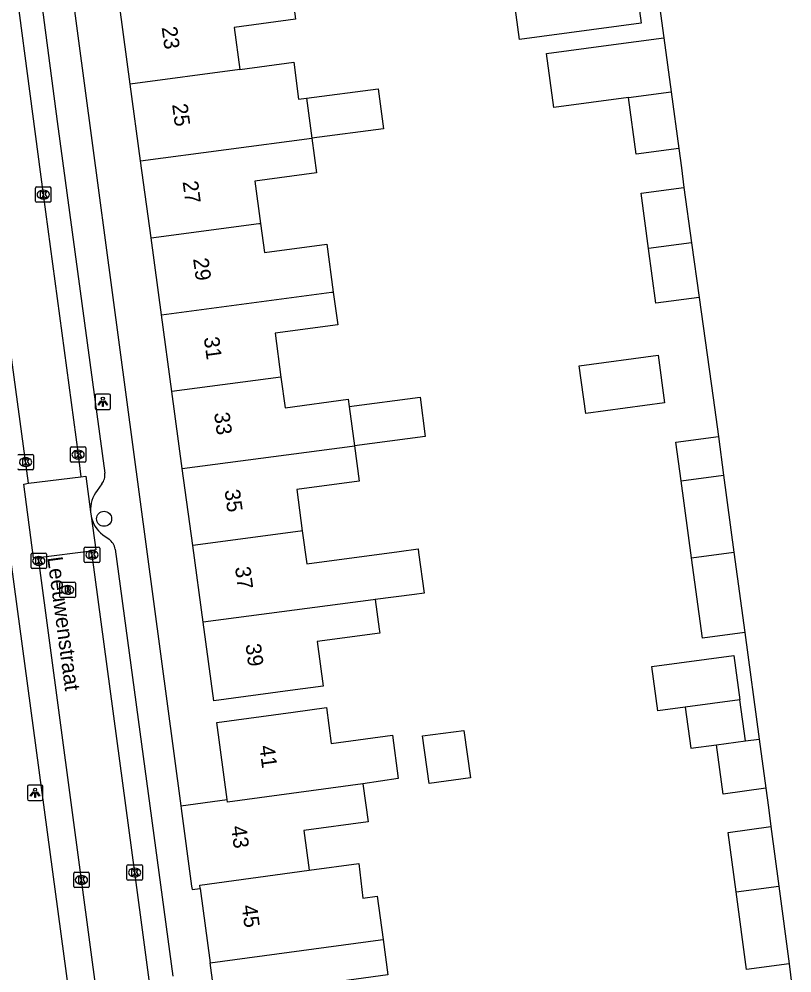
# Model space of a CAD drawing. Extents: x 163150 to 163546, y 380933 to 381635.
# Drawn here: x 163474.3 to 163524.5, y 381366 to 381427.9 of the extents above; entities that cross this region are included whole.
import ezdxf

# ---------------------------------------------------------------- set-up
doc = ezdxf.new("R2010")
doc.units = 0
for name, color, linetype in [('IMGEO_Boom', 7, 'Continuous'), ('IMGEO_Kolk', 7, 'Continuous'), ('IMGEO_Lichtpunt', 7, 'Continuous'), ('IMGEO_Openbare_ruimte_label', 7, 'Continuous'), ('IMGEO_Pand', 7, 'Continuous'), ('IMGEO_Pand_nummerreeks', 7, 'Continuous'), ('IMGEO_Rijbaan_lokaal_open', 7, 'Continuous'), ('IMGEO_Rioolput', 7, 'Continuous'), ('IMGEO_Voetpad_open', 7, 'Continuous')]:
    doc.layers.add(name, color=color, linetype=linetype)

msp = doc.modelspace()

# ---------------------------------------------------------------- linework, layer by layer
at = {"layer": 'IMGEO_Boom'}
msp.add_circle((163479.854, 381395.496), 0.489, dxfattribs=at)
at = {"layer": 'IMGEO_Kolk'}
for p, q in [((163475.408, 381416.117), (163475.408, 381416.969)), ((163475.483, 381417.043), (163476.335, 381417.043)), ((163476.409, 381416.969), (163476.409, 381416.117)), ((163475.919, 381416.263), (163475.894, 381416.263)), ((163475.896, 381416.823), (163475.921, 381416.823)), ((163476.335, 381416.043), (163475.483, 381416.043)), ((163477.742, 381400.167), (163478.594, 381400.167)), ((163474.337, 381399.678), (163475.189, 381399.678)), ((163475.263, 381399.604), (163475.263, 381398.752)), ((163477.667, 381399.241), (163477.667, 381400.093)), ((163478.155, 381399.947), (163478.18, 381399.947)), ((163478.668, 381400.093), (163478.668, 381399.241)), ((163474.75, 381399.458), (163474.775, 381399.458)), ((163478.594, 381399.167), (163477.742, 381399.167)), ((163478.178, 381399.387), (163478.153, 381399.387)), ((163475.189, 381398.678), (163474.337, 381398.678)), ((163474.773, 381398.898), (163474.748, 381398.898)), ((163478.569, 381392.732), (163478.569, 381393.584)), ((163478.644, 381393.658), (163479.496, 381393.658)), ((163479.057, 381393.438), (163479.082, 381393.438)), ((163479.57, 381393.584), (163479.57, 381392.732)), ((163475.113, 381392.339), (163475.113, 381393.191)), ((163475.188, 381393.265), (163476.04, 381393.265)), ((163475.601, 381393.045), (163475.626, 381393.045)), ((163476.114, 381393.191), (163476.114, 381392.339)), ((163479.08, 381392.878), (163479.055, 381392.878)), ((163476.04, 381392.265), (163475.188, 381392.265)), ((163475.624, 381392.485), (163475.599, 381392.485)), ((163479.496, 381392.658), (163478.644, 381392.658)), ((163481.339, 381372.106), (163481.339, 381372.958)), ((163481.414, 381373.032), (163482.266, 381373.032)), ((163482.34, 381372.958), (163482.34, 381372.106)), ((163477.885, 381371.623), (163477.885, 381372.475)), ((163477.96, 381372.549), (163478.812, 381372.549)), ((163478.373, 381372.329), (163478.398, 381372.329)), ((163478.886, 381372.475), (163478.886, 381371.623)), ((163481.827, 381372.812), (163481.852, 381372.812)), ((163478.396, 381371.769), (163478.371, 381371.769)), ((163482.266, 381372.032), (163481.414, 381372.032)), ((163481.85, 381372.252), (163481.825, 381372.252)), ((163478.812, 381371.549), (163477.96, 381371.549))]:
    msp.add_line(p, q, dxfattribs=at)
for points in [[(163475.408, 381416.117), (163475.408, 381416.969)], [(163475.483, 381417.043), (163476.335, 381417.043)], [(163476.409, 381416.969), (163476.409, 381416.117)], [(163475.729, 381416.743), (163475.852, 381416.743), (163475.852, 381416.592), (163475.982, 381416.743), (163476.146, 381416.743), (163476, 381416.592), (163476.153, 381416.343), (163476.001, 381416.343), (163475.916, 381416.507), (163475.852, 381416.44), (163475.852, 381416.343), (163475.729, 381416.343), (163475.729, 381416.743)], [(163476.335, 381416.043), (163475.483, 381416.043)], [(163477.742, 381400.167), (163478.594, 381400.167)], [(163474.337, 381399.678), (163475.189, 381399.678)], [(163475.263, 381399.604), (163475.263, 381398.752)], [(163477.667, 381399.241), (163477.667, 381400.093)], [(163477.988, 381399.867), (163478.111, 381399.867), (163478.111, 381399.716), (163478.241, 381399.867), (163478.405, 381399.867), (163478.259, 381399.716), (163478.412, 381399.467), (163478.26, 381399.467), (163478.175, 381399.631), (163478.111, 381399.564), (163478.111, 381399.467), (163477.988, 381399.467), (163477.988, 381399.867)], [(163478.668, 381400.093), (163478.668, 381399.241)], [(163474.583, 381399.378), (163474.706, 381399.378), (163474.706, 381399.227), (163474.836, 381399.378), (163475, 381399.378), (163474.854, 381399.227), (163475.007, 381398.978), (163474.855, 381398.978), (163474.77, 381399.142), (163474.706, 381399.075), (163474.706, 381398.978), (163474.583, 381398.978), (163474.583, 381399.378)], [(163478.594, 381399.167), (163477.742, 381399.167)], [(163475.189, 381398.678), (163474.337, 381398.678)], [(163478.569, 381392.732), (163478.569, 381393.584)], [(163478.644, 381393.658), (163479.496, 381393.658)], [(163478.89, 381393.358), (163479.013, 381393.358), (163479.013, 381393.207), (163479.143, 381393.358), (163479.307, 381393.358), (163479.161, 381393.207), (163479.314, 381392.958), (163479.162, 381392.958), (163479.077, 381393.122), (163479.013, 381393.055), (163479.013, 381392.958), (163478.89, 381392.958), (163478.89, 381393.358)], [(163479.57, 381393.584), (163479.57, 381392.732)], [(163475.113, 381392.339), (163475.113, 381393.191)], [(163475.188, 381393.265), (163476.04, 381393.265)], [(163475.434, 381392.965), (163475.557, 381392.965), (163475.557, 381392.814), (163475.687, 381392.965), (163475.851, 381392.965), (163475.705, 381392.814), (163475.858, 381392.565), (163475.706, 381392.565), (163475.621, 381392.729), (163475.557, 381392.662), (163475.557, 381392.565), (163475.434, 381392.565), (163475.434, 381392.965)], [(163476.114, 381393.191), (163476.114, 381392.339)], [(163476.04, 381392.265), (163475.188, 381392.265)], [(163479.496, 381392.658), (163478.644, 381392.658)], [(163481.339, 381372.106), (163481.339, 381372.958)], [(163481.414, 381373.032), (163482.266, 381373.032)], [(163482.34, 381372.958), (163482.34, 381372.106)], [(163477.885, 381371.623), (163477.885, 381372.475)], [(163477.96, 381372.549), (163478.812, 381372.549)], [(163478.886, 381372.475), (163478.886, 381371.623)], [(163481.66, 381372.732), (163481.783, 381372.732), (163481.783, 381372.581), (163481.913, 381372.732), (163482.077, 381372.732), (163481.931, 381372.581), (163482.084, 381372.332), (163481.932, 381372.332), (163481.847, 381372.496), (163481.783, 381372.429), (163481.783, 381372.332), (163481.66, 381372.332), (163481.66, 381372.732)], [(163478.206, 381372.249), (163478.329, 381372.249), (163478.329, 381372.098), (163478.459, 381372.249), (163478.623, 381372.249), (163478.477, 381372.098), (163478.63, 381371.849), (163478.478, 381371.849), (163478.393, 381372.013), (163478.329, 381371.946), (163478.329, 381371.849), (163478.206, 381371.849), (163478.206, 381372.249)], [(163482.266, 381372.032), (163481.414, 381372.032)], [(163478.812, 381371.549), (163477.96, 381371.549)]]:
    msp.add_lwpolyline(points, dxfattribs=at)
for centre, start, end in [((163475.485, 381416.967), 91.55205, 178.44795), ((163475.485, 381416.967), 91.55205, 178.44795), ((163476.333, 381416.967), 1.55205, 88.44795), ((163476.333, 381416.967), 1.55205, 88.44795), ((163475.485, 381416.119), 181.55205, 268.44795), ((163475.485, 381416.119), 181.55205, 268.44795), ((163476.333, 381416.119), 271.55205, 358.44795), ((163476.333, 381416.119), 271.55205, 358.44795), ((163477.744, 381400.091), 91.55205, 178.44795), ((163477.744, 381400.091), 91.55205, 178.44795), ((163478.592, 381400.091), 1.55205, 88.44795), ((163478.592, 381400.091), 1.55205, 88.44795), ((163474.339, 381399.602), 91.55205, 178.44795), ((163474.339, 381399.602), 91.55205, 178.44795), ((163475.187, 381399.602), 1.55205, 88.44795), ((163475.187, 381399.602), 1.55205, 88.44795), ((163477.744, 381399.243), 181.55205, 268.44795), ((163477.744, 381399.243), 181.55205, 268.44795), ((163478.592, 381399.243), 271.55205, 358.44795), ((163478.592, 381399.243), 271.55205, 358.44795), ((163474.339, 381398.754), 181.55205, 268.44795), ((163474.339, 381398.754), 181.55205, 268.44795), ((163475.187, 381398.754), 271.55205, 358.44795), ((163475.187, 381398.754), 271.55205, 358.44795), ((163478.646, 381393.582), 91.55205, 178.44795), ((163478.646, 381393.582), 91.55205, 178.44795), ((163479.494, 381393.582), 1.55205, 88.44795), ((163479.494, 381393.582), 1.55205, 88.44795), ((163475.19, 381393.189), 91.55205, 178.44795), ((163475.19, 381393.189), 91.55205, 178.44795), ((163476.038, 381393.189), 1.55205, 88.44795), ((163476.038, 381393.189), 1.55205, 88.44795), ((163478.646, 381392.734), 181.55205, 268.44795), ((163478.646, 381392.734), 181.55205, 268.44795), ((163479.494, 381392.734), 271.55205, 358.44795), ((163479.494, 381392.734), 271.55205, 358.44795), ((163475.19, 381392.341), 181.55205, 268.44795), ((163475.19, 381392.341), 181.55205, 268.44795), ((163476.038, 381392.341), 271.55205, 358.44795), ((163476.038, 381392.341), 271.55205, 358.44795), ((163481.416, 381372.956), 91.55205, 178.44795), ((163481.416, 381372.956), 91.55205, 178.44795), ((163482.264, 381372.956), 1.55205, 88.44795), ((163482.264, 381372.956), 1.55205, 88.44795), ((163477.962, 381372.473), 91.55205, 178.44795), ((163477.962, 381372.473), 91.55205, 178.44795), ((163478.81, 381372.473), 1.55205, 88.44795), ((163478.81, 381372.473), 1.55205, 88.44795), ((163481.416, 381372.108), 181.55205, 268.44795), ((163481.416, 381372.108), 181.55205, 268.44795), ((163482.264, 381372.108), 271.55205, 358.44795), ((163482.264, 381372.108), 271.55205, 358.44795), ((163477.962, 381371.625), 181.55205, 268.44795), ((163477.962, 381371.625), 181.55205, 268.44795), ((163478.81, 381371.625), 271.55205, 358.44795), ((163478.81, 381371.625), 271.55205, 358.44795)]:
    msp.add_arc(centre, 0.0765, start, end, dxfattribs=at)
for centre, major_axis, ratio, start_param, end_param in [((163475.895, 381416.543), (-0.387, 0.002), 0.722429, 4.712389, 7.853982), ((163475.92, 381416.543), (-0.39, 0.002), 0.717154, 1.570796, 4.712389), ((163478.154, 381399.667), (-0.387, 0.002), 0.722429, 4.712389, 7.853982), ((163478.179, 381399.667), (-0.39, 0.002), 0.717154, 1.570796, 4.712389), ((163474.749, 381399.178), (-0.387, 0.002), 0.722429, 4.712389, 7.853982), ((163474.774, 381399.178), (-0.39, 0.002), 0.717154, 1.570796, 4.712389), ((163479.056, 381393.158), (-0.387, 0.002), 0.722429, 4.712389, 7.853982), ((163479.081, 381393.158), (-0.39, 0.002), 0.717154, 1.570796, 4.712389), ((163475.6, 381392.765), (-0.387, 0.002), 0.722429, 4.712389, 7.853982), ((163475.625, 381392.765), (-0.39, 0.002), 0.717154, 1.570796, 4.712389), ((163478.372, 381372.049), (-0.387, 0.002), 0.722429, 4.712389, 7.853982), ((163478.397, 381372.049), (-0.39, 0.002), 0.717154, 1.570796, 4.712389), ((163481.826, 381372.532), (-0.387, 0.002), 0.722429, 4.712389, 7.853982), ((163481.851, 381372.532), (-0.39, 0.002), 0.717154, 1.570796, 4.712389)]:
    msp.add_ellipse(centre, major_axis=major_axis, ratio=ratio, start_param=start_param, end_param=end_param, dxfattribs=at)
at = {"layer": 'IMGEO_Lichtpunt'}
for p, q in [((163479.275, 381403.5), (163479.275, 381402.693)), ((163479.275, 381403.5), (163479.275, 381402.693)), ((163480.177, 381403.595), (163479.369, 381403.595)), ((163480.177, 381403.595), (163479.369, 381403.595)), ((163480.271, 381402.693), (163480.271, 381403.5)), ((163480.271, 381402.693), (163480.271, 381403.5)), ((163479.369, 381402.599), (163480.177, 381402.599)), ((163479.369, 381402.599), (163480.177, 381402.599)), ((163474.879, 381378.112), (163474.879, 381377.305)), ((163474.879, 381378.112), (163474.879, 381377.305)), ((163475.781, 381378.207), (163474.973, 381378.207)), ((163475.781, 381378.207), (163474.973, 381378.207)), ((163475.875, 381377.305), (163475.875, 381378.112)), ((163475.875, 381377.305), (163475.875, 381378.112)), ((163474.973, 381377.211), (163475.781, 381377.211)), ((163474.973, 381377.211), (163475.781, 381377.211))]:
    msp.add_line(p, q, dxfattribs=at)
for points in [[(163479.649, 381403.164), (163479.688, 381403.136), (163479.5, 381402.874), (163479.462, 381402.901), (163479.649, 381403.164)], [(163479.751, 381403.116), (163479.798, 381403.116), (163479.798, 381402.794), (163479.751, 381402.794), (163479.751, 381403.116)], [(163479.861, 381403.136), (163479.899, 381403.163), (163480.086, 381402.901), (163480.047, 381402.873), (163479.861, 381403.136)], [(163475.253, 381377.776), (163475.292, 381377.748), (163475.104, 381377.486), (163475.066, 381377.513), (163475.253, 381377.776)], [(163475.355, 381377.728), (163475.402, 381377.728), (163475.402, 381377.406), (163475.355, 381377.406), (163475.355, 381377.728)], [(163475.465, 381377.748), (163475.503, 381377.775), (163475.69, 381377.513), (163475.651, 381377.485), (163475.465, 381377.748)]]:
    msp.add_lwpolyline(points, dxfattribs=at)
for centre in [(163479.774, 381403.298), (163475.378, 381377.91)]:
    msp.add_circle(centre, 0.0994, dxfattribs=at)
for centre, start, end in [((163479.369, 381403.5), 90, 180), ((163479.369, 381403.5), 90, 180), ((163480.177, 381403.5), 0, 90), ((163480.177, 381403.5), 0, 90), ((163479.369, 381402.693), 180, 270), ((163479.369, 381402.693), 180, 270), ((163480.177, 381402.693), 270, 0), ((163480.177, 381402.693), 270, 360), ((163474.973, 381378.112), 90, 180), ((163474.973, 381378.112), 90, 180), ((163475.781, 381378.112), 0, 90), ((163475.781, 381378.112), 0, 90), ((163474.973, 381377.305), 180, 270), ((163474.973, 381377.305), 180, 270), ((163475.781, 381377.305), 270, 0), ((163475.781, 381377.305), 270, 360)]:
    msp.add_arc(centre, 0.0946, start, end, dxfattribs=at)
at = {"layer": 'IMGEO_Pand'}
for points in [[(163506.833, 381426.603), (163506.355, 381430.159), (163514.248, 381431.22), (163514.726, 381427.665), (163506.833, 381426.603)], [(163491.974, 381430.18), (163492.276, 381427.934), (163488.3, 381427.4), (163488.668, 381424.662)], [(163481.545, 381423.722), (163480.867, 381428.714)], [(163513.895, 381422.846), (163509.052, 381422.198), (163508.58, 381425.707), (163512.591, 381426.247), (163516.19, 381426.731)], [(163516.19, 381426.731), (163516.67, 381423.217)], [(163488.668, 381424.662), (163492.165, 381425.131), (163492.482, 381422.733), (163492.992, 381422.801)], [(163488.668, 381424.662), (163481.545, 381423.722)], [(163482.223, 381418.73), (163481.545, 381423.722)], [(163492.992, 381422.801), (163497.657, 381423.416), (163498.001, 381420.813), (163493.341, 381420.198)], [(163513.895, 381422.846), (163516.67, 381423.217)], [(163516.67, 381423.217), (163517.164, 381419.527)], [(163492.992, 381422.801), (163493.341, 381420.198)], [(163517.164, 381419.527), (163514.388, 381419.161), (163513.895, 381422.846)], [(163482.223, 381418.73), (163493.341, 381420.198)], [(163493.341, 381420.198), (163493.642, 381417.959), (163489.65, 381417.423), (163490.019, 381414.678)], [(163482.902, 381413.738), (163482.223, 381418.73)], [(163515.206, 381413.044), (163514.724, 381416.647), (163517.5, 381417.013)], [(163517.5, 381417.013), (163517.982, 381413.416)], [(163482.902, 381413.738), (163489.893, 381414.661), (163490.019, 381414.678)], [(163490.019, 381414.678), (163490.274, 381412.777), (163494.319, 381413.32), (163494.736, 381410.219)], [(163483.579, 381408.747), (163482.902, 381413.738)], [(163517.982, 381413.416), (163515.206, 381413.044)], [(163517.982, 381413.416), (163518.483, 381409.86)], [(163518.483, 381409.86), (163515.682, 381409.485), (163515.206, 381413.044)], [(163483.579, 381408.747), (163494.619, 381410.204), (163494.736, 381410.219)], [(163494.736, 381410.219), (163495.021, 381408.095), (163490.955, 381407.549), (163491.339, 381404.69)], [(163484.258, 381403.755), (163483.579, 381408.747)], [(163510.705, 381405.428), (163515.819, 381406.117), (163516.237, 381403.016), (163511.122, 381402.327), (163510.705, 381405.428)], [(163491.339, 381404.69), (163484.258, 381403.755)], [(163491.339, 381404.69), (163491.605, 381402.71), (163495.699, 381403.26), (163495.761, 381402.794)], [(163484.935, 381398.764), (163484.258, 381403.755)], [(163495.761, 381402.794), (163500.373, 381403.403), (163500.71, 381400.847), (163496.104, 381400.239)], [(163495.761, 381402.794), (163496.104, 381400.239)], [(163517.321, 381397.955), (163516.983, 381400.466), (163519.738, 381400.837)], [(163519.738, 381400.837), (163520.077, 381398.319)], [(163484.935, 381398.764), (163495.97, 381400.221), (163496.104, 381400.239)], [(163496.104, 381400.239), (163496.414, 381397.933), (163492.36, 381397.389), (163492.72, 381394.71)], [(163485.614, 381393.772), (163484.935, 381398.764)], [(163517.321, 381397.955), (163520.077, 381398.319)], [(163520.077, 381398.319), (163520.748, 381393.329)], [(163517.992, 381392.965), (163517.321, 381397.955)], [(163492.72, 381394.71), (163492.602, 381394.694), (163485.614, 381393.772)], [(163492.72, 381394.71), (163493.007, 381392.571), (163499.015, 381393.378), (163500.244, 381393.543), (163500.275, 381393.303), (163500.627, 381390.674), (163500, 381390.591), (163497.459, 381390.255)], [(163486.291, 381388.781), (163485.614, 381393.772)], [(163517.992, 381392.965), (163520.748, 381393.329)], [(163521.449, 381388.117), (163518.694, 381387.746), (163517.992, 381392.965)], [(163520.748, 381393.329), (163521.449, 381388.117)], [(163497.459, 381390.255), (163497.718, 381388.322), (163497.752, 381388.068), (163493.695, 381387.523), (163494.084, 381384.631), (163491.941, 381384.341), (163486.986, 381383.668), (163486.291, 381388.781)], [(163497.459, 381390.255), (163497.322, 381390.237), (163486.291, 381388.781)], [(163517.586, 381383.268), (163515.807, 381383.029), (163515.421, 381385.905), (163520.743, 381386.62), (163521.129, 381383.744)], [(163521.129, 381383.744), (163517.586, 381383.268)], [(163521.488, 381381.076), (163521.129, 381383.744)], [(163487.847, 381377.266), (163487.174, 381382.276), (163492.13, 381382.945), (163494.29, 381383.237), (163494.603, 381380.905), (163498.578, 381381.439), (163498.956, 381378.626), (163496.657, 381378.292)], [(163517.586, 381383.268), (163517.945, 381380.599), (163519.608, 381380.823)], [(163503.217, 381381.762), (163503.639, 381378.681), (163500.958, 381378.314), (163500.536, 381381.395), (163503.217, 381381.762)], [(163519.608, 381380.823), (163521.488, 381381.076)], [(163521.488, 381381.076), (163522.383, 381381.196)], [(163522.383, 381381.196), (163522.812, 381378)], [(163522.812, 381378), (163520.037, 381377.626), (163519.608, 381380.823)], [(163496.657, 381378.292), (163487.869, 381377.103), (163487.847, 381377.266)], [(163496.657, 381378.292), (163496.989, 381375.825), (163492.827, 381375.266), (163493.175, 381372.676)], [(163484.837, 381376.861), (163487.847, 381377.266)], [(163484.837, 381376.861), (163484.859, 381376.696), (163485.538, 381371.644), (163485.566, 381371.433), (163486.09, 381371.504)], [(163520.891, 381371.273), (163520.371, 381375.139), (163523.145, 381375.513)], [(163523.145, 381375.513), (163523.654, 381371.653)], [(163493.175, 381372.676), (163496.399, 381373.112), (163496.661, 381370.866), (163497.59, 381370.991), (163497.967, 381368.18)], [(163486.09, 381371.504), (163486.062, 381371.715), (163493.175, 381372.676)], [(163486.09, 381371.504), (163486.74, 381366.662)], [(163520.891, 381371.273), (163523.654, 381371.653)], [(163524.321, 381366.6), (163521.57, 381366.228), (163520.891, 381371.273)], [(163523.654, 381371.653), (163524.321, 381366.6)], [(163486.74, 381366.662), (163497.804, 381368.158), (163497.967, 381368.18)], [(163497.967, 381368.18), (163498.276, 381365.88), (163494.156, 381365.327), (163494.527, 381362.57)], [(163487.388, 381361.841), (163486.74, 381366.662)]]:
    msp.add_lwpolyline(points, dxfattribs=at)
at = {"layer": 'IMGEO_Rijbaan_lokaal_open'}
for points in [[(163470.778, 381454.762), (163470.878, 381454.101), (163473.318, 381436.048), (163475.908, 381416.544), (163478.167, 381399.667), (163478.336, 381398.227)], [(163474.95, 381397.812), (163472.424, 381416.369), (163471.932, 381420.183), (163469.84, 381435.559), (163467.375, 381453.632), (163467.333, 381454.278)], [(163513.109, 381449.351), (163513.265, 381448.139), (163516.19, 381426.731)], [(163517.164, 381419.527), (163517.33, 381418.283), (163517.5, 381417.013)], [(163518.483, 381409.86), (163519.399, 381403.356), (163519.738, 381400.837)], [(163475.57, 381392.982), (163475.27, 381392.965), (163474.636, 381397.753), (163474.95, 381397.812)], [(163474.95, 381397.812), (163478.336, 381398.227)], [(163478.336, 381398.227), (163478.665, 381398.259), (163478.975, 381395.958)], [(163478.975, 381395.958), (163479.015, 381395.662)], [(163479.015, 381395.662), (163479.31, 381393.474), (163479.013, 381393.424)], [(163475.57, 381392.982), (163479.013, 381393.424)], [(163479.013, 381393.424), (163479.069, 381393.155), (163481.839, 381372.532), (163484.475, 381352.776), (163487.265, 381332.107), (163487.676, 381329.103)], [(163484.25, 381328.608), (163483.846, 381331.616), (163481.014, 381352.472), (163478.387, 381372.049), (163475.613, 381392.784), (163475.57, 381392.982)], [(163521.449, 381388.117), (163522.383, 381381.196)], [(163522.812, 381378), (163522.981, 381376.759), (163523.145, 381375.513)], [(163524.321, 381366.6), (163524.509, 381365.17)]]:
    msp.add_lwpolyline(points, dxfattribs=at)
at = {"layer": 'IMGEO_Rioolput'}
for p, q in [((163476.992, 381390.457), (163476.992, 381391.309)), ((163477.067, 381391.383), (163477.919, 381391.383)), ((163477.48, 381391.163), (163477.505, 381391.163)), ((163477.993, 381391.309), (163477.993, 381390.457)), ((163477.919, 381390.383), (163477.067, 381390.383)), ((163477.503, 381390.603), (163477.478, 381390.603))]:
    msp.add_line(p, q, dxfattribs=at)
for points in [[(163476.992, 381390.457), (163476.992, 381391.309)], [(163477.067, 381391.383), (163477.919, 381391.383)], [(163477.581, 381391.081), (163477.329, 381391.083), (163477.329, 381390.683)], [(163477.507, 381391.002), (163477.453, 381391.002), (163477.453, 381390.921)], [(163477.453, 381390.921), (163477.505, 381390.921)], [(163477.993, 381391.309), (163477.993, 381390.457)], [(163477.919, 381390.383), (163477.067, 381390.383)], [(163477.329, 381390.683), (163477.453, 381390.683), (163477.453, 381390.845), (163477.464, 381390.845)], [(163477.511, 381390.816), (163477.582, 381390.683), (163477.722, 381390.683), (163477.657, 381390.809)]]:
    msp.add_lwpolyline(points, dxfattribs=at)
for centre, radius, start, end in [((163477.069, 381391.307), 0.0765, 91.55205, 178.44795), ((163477.069, 381391.307), 0.0765, 91.55205, 178.44795), ((163477.489, 381391.11), 0.19, 274.7715, 282.96867), ((163477.513, 381390.906), 0.0964, 77.00612, 93.18647), ((163477.527, 381390.963), 0.0378, 276.66336, 79.67722), ((163477.58, 381390.971), 0.109, 350.36119, 89.41601), ((163477.578, 381390.971), 0.112, 277.58423, 350.98172), ((163477.562, 381390.756), 0.108, 29.51342, 73.79051), ((163477.917, 381391.307), 0.0765, 1.55205, 88.44795), ((163477.917, 381391.307), 0.0765, 1.55205, 88.44795), ((163477.069, 381390.459), 0.0765, 181.55205, 268.44795), ((163477.069, 381390.459), 0.0765, 181.55205, 268.44795), ((163477.463, 381390.792), 0.0533, 26.02933, 88.69889), ((163477.917, 381390.459), 0.0765, 271.55205, 358.44795), ((163477.917, 381390.459), 0.0765, 271.55205, 358.44795)]:
    msp.add_arc(centre, radius, start, end, dxfattribs=at)
for centre, major_axis, ratio, start_param, end_param in [((163477.479, 381390.883), (-0.387, 0.002), 0.722429, 4.712389, 7.853982), ((163477.504, 381390.883), (-0.39, 0.002), 0.717154, 1.570796, 4.712389)]:
    msp.add_ellipse(centre, major_axis=major_axis, ratio=ratio, start_param=start_param, end_param=end_param, dxfattribs=at)
at = {"layer": 'IMGEO_Voetpad_open'}
for points in [[(163474.607, 381453.41), (163484.837, 381376.861)], [(163475.395, 381432.031), (163476.816, 381421.298), (163479.901, 381398.456)], [(163480.813, 381340.703), (163470.252, 381419.099)], [(163479.702, 381397.757), (163479.399, 381397.332)], [(163479.767, 381394.465), (163480.177, 381394.171)], [(163480.585, 381393.522), (163484.323, 381365.797)]]:
    msp.add_lwpolyline(points, dxfattribs=at)
for centre, radius, start, end in [((163479.02, 381398.329), 0.89, 320.01842, 8.19908), ((163481.011, 381396.082), 2.039, 142.20662, 183.49418), ((163481.009, 381396.08), 2.038, 191.84275, 232.43439), ((163479.503, 381393.294), 1.106, 11.88241, 52.42941)]:
    msp.add_arc(centre, radius, start, end, dxfattribs=at)

# ---------------------------------------------------------------- texts
at = {"layer": 'IMGEO_Openbare_ruimte_label'}
msp.add_text('Leeuwenstraat', height=1, rotation=277.64387, dxfattribs=at).set_placement((163476.165, 381392.975))
at = {"layer": 'IMGEO_Pand_nummerreeks'}
for s, rotation, p in [('23', 277.7353, (163483.59, 381427.4)), ('25', 277.73472, (163484.269, 381422.391)), ('27', 277.7353, (163484.95, 381417.382)), ('29', 277.7353, (163485.631, 381412.374)), ('31', 277.7353, (163486.326, 381407.254)), ('33', 277.73472, (163486.99, 381402.356)), ('35', 277.7353, (163487.672, 381397.347)), ('37', 277.73472, (163488.351, 381392.339)), ('39', 277.73472, (163489.031, 381387.33)), ('41', 277.64878, (163489.925, 381380.732)), ('43', 277.64878, (163488.094, 381375.515)), ('45', 277.64878, (163488.785, 381370.373))]:
    msp.add_text(s, height=1, rotation=rotation, dxfattribs=at).set_placement(p)

doc.saveas('drawing.dxf')
